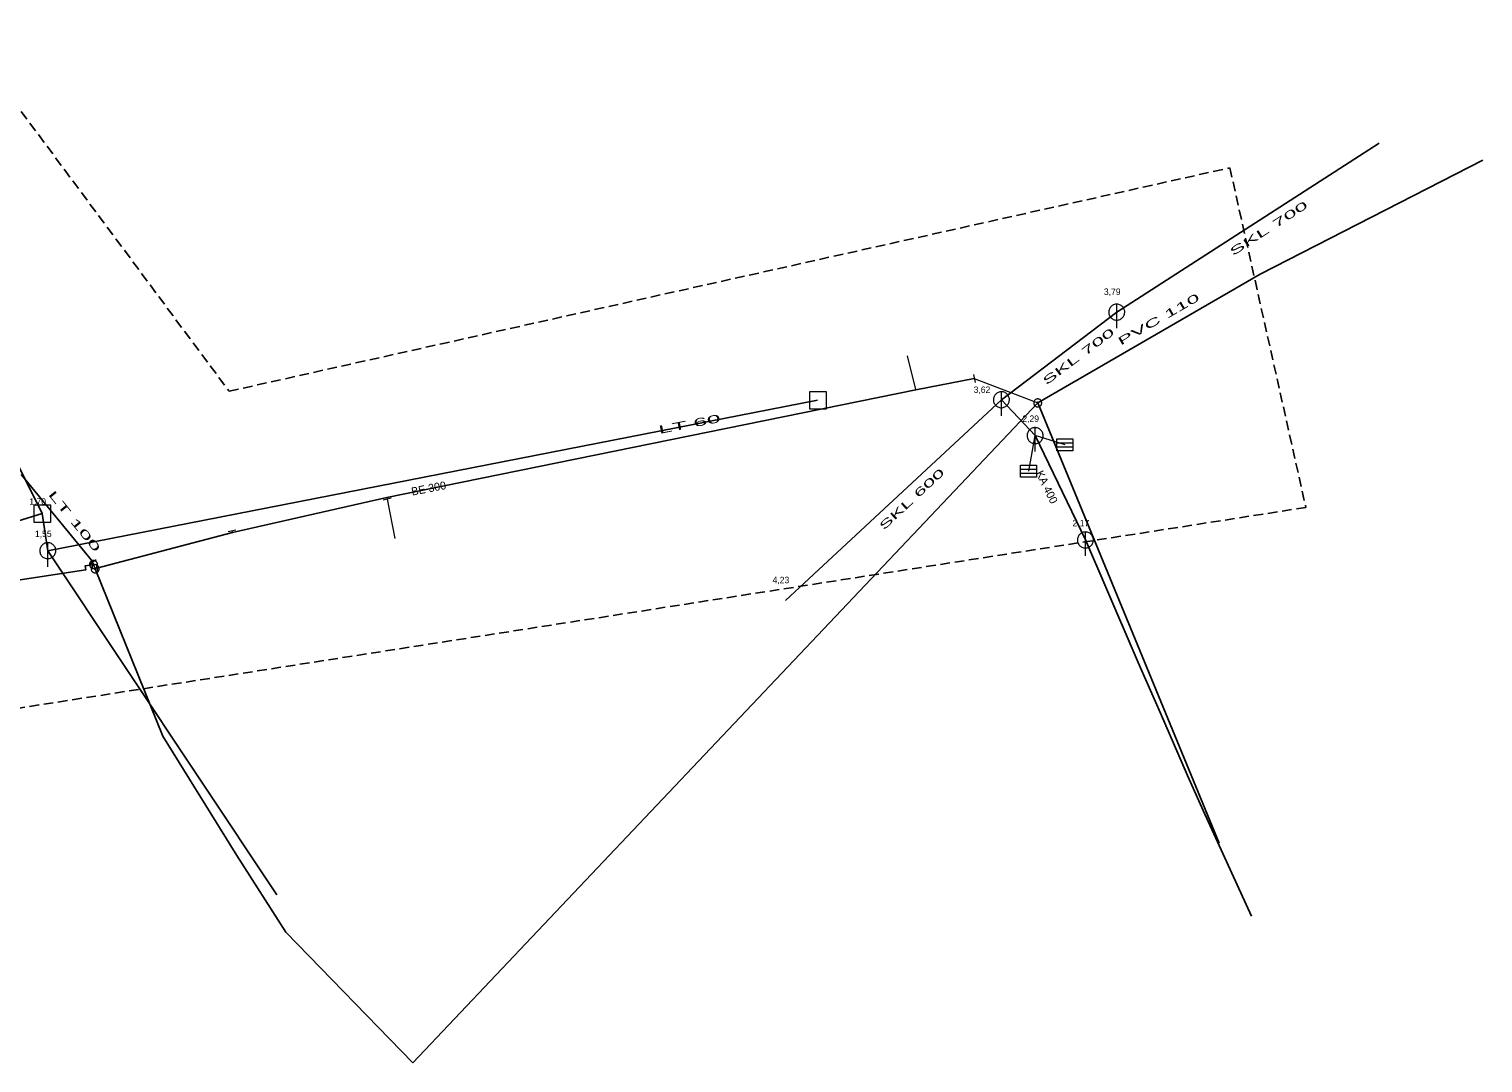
# Model space of a CAD drawing. Extents: x -689820 to -689363, y -975369 to -975062.
# Drawn here: x -689544.2 to -689362.6, y -975351.8 to -975222.7 of the extents above; entities that cross this region are included whole.
import ezdxf

# ---------------------------------------------------------------- set-up
doc = ezdxf.new("R2010")
doc.units = 0
doc.header["$LTSCALE"] = 0.4
doc.linetypes.add('MEDIUM_DASHED', pattern=[4.5, 3, -1.5])
doc.layers.add('1', color=7, linetype='Continuous')
for name, color, linetype, lineweight in [('11', 7, 'Continuous', 13), ('13', 7, 'Continuous', 13), ('14', 7, 'Continuous', 25), ('17', 7, 'Continuous', 25), ('22', 7, 'Continuous', 13), ('34', 7, 'Continuous', 13), ('47', 7, 'Continuous', 13), ('63', 7, 'MEDIUM_DASHED', 25)]:
    doc.layers.add(name, color=color, linetype=linetype, lineweight=lineweight)

msp = doc.modelspace()

# ---------------------------------------------------------------- linework, layer by layer
at = {"layer": '11'}
for p in [(-689419.3, -975277.91), (-689414.76, -975274.629)]:
    msp.add_line(p, (-689418.5, -975273.46), dxfattribs=at)
at = {"layer": '13'}
for p, q in [((-689433.4, -975267.707), (-689434.429, -975263.493)), ((-689499.459, -975281.399), (-689498.509, -975286.309))]:
    msp.add_line(p, q, dxfattribs=at)
at = {"layer": '14'}
for p, q in [((-689408.307, -975258.04), (-689375.534, -975236.952)), ((-689445.682, -975269.038), (-689541.87, -975287.838)), ((-689418.5, -975273.46), (-689422.719, -975268.98)), ((-689412.219, -975286.5), (-689418.5, -975273.46)), ((-689541.87, -975287.838), (-689542.572, -975283.204)), ((-689513.237, -975330.816), (-689541.87, -975287.838))]:
    msp.add_line(p, q, dxfattribs=at)
at = {"layer": '14', "lineweight": 13}
for p, q in [((-689426.099, -975266.339), (-689418.177, -975269.382)), ((-689433.388, -975267.761), (-689433.4, -975267.707)), ((-689499.505, -975281.209), (-689499.459, -975281.399)), ((-689518.795, -975285.558), (-689518.848, -975285.325)), ((-689536.162, -975289.569), (-689536.351, -975289.602)), ((-689536.162, -975289.569), (-689536.239, -975289.23)), ((-689535.949, -975290.109), (-689536.162, -975289.569)), ((-689535.721, -975290.003), (-689535.949, -975290.109))]:
    msp.add_line(p, q, dxfattribs=at)
at = {"layer": '14'}
for points in [[(-689449.708, -975294.055), (-689422.719, -975268.98), (-689408.307, -975258.04)], [(-689583.441, -975293.556), (-689564.324, -975289.938), (-689542.572, -975283.204), (-689553.342, -975261.657)], [(-689391.449, -975333.51), (-689397.489, -975320.28), (-689399.46, -975315.92), (-689402.838, -975308.133), (-689405.32, -975302.467), (-689405.75, -975301.5), (-689409.66, -975292.403), (-689412.219, -975286.5)]]:
    msp.add_lwpolyline(points, dxfattribs=at)
at = {"layer": '17'}
for p, q in [((-689418.177, -975269.382), (-689496.251, -975351.823)), ((-689395.493, -975324.391), (-689418.177, -975269.382)), ((-689536.239, -975289.23), (-689545.213, -975278.312))]:
    msp.add_line(p, q, dxfattribs=at)
for points in [[(-689362.55, -975239.05), (-689390.403, -975253.287), (-689418.177, -975269.382)], [(-689426.099, -975266.339), (-689433.388, -975267.761), (-689499.505, -975281.209), (-689518.795, -975285.558), (-689535.721, -975290.003)], [(-689536.351, -975289.602), (-689537.203, -975289.743), (-689537.12, -975290.232), (-689713.89, -975317.113)], [(-689496.251, -975351.823), (-689512.116, -975335.5), (-689518.26, -975325.93), (-689527.5, -975310.989), (-689535.949, -975290.109)]]:
    msp.add_lwpolyline(points, dxfattribs=at)
at = {"layer": '22'}
for p, q in [((-689408.307, -975260.04), (-689408.306, -975257.04)), ((-689422.719, -975270.98), (-689422.718, -975267.98)), ((-689418.5, -975275.46), (-689418.499, -975272.46)), ((-689415.771, -975274.372), (-689413.771, -975274.372)), ((-689415.771, -975274.872), (-689413.771, -975274.872)), ((-689420.311, -975277.653), (-689418.311, -975277.653)), ((-689420.311, -975278.153), (-689418.311, -975278.153)), ((-689541.87, -975289.838), (-689541.869, -975286.838)), ((-689412.219, -975288.5), (-689412.218, -975285.5))]:
    msp.add_line(p, q, dxfattribs=at)
for points in [[(-689407.307, -975258.04), (-689407.312, -975257.931), (-689407.33, -975257.823), (-689407.36, -975257.717), (-689407.4, -975257.616), (-689407.452, -975257.519), (-689407.514, -975257.429), (-689407.586, -975257.346), (-689407.666, -975257.272), (-689407.754, -975257.206), (-689407.848, -975257.151), (-689407.948, -975257.106), (-689408.053, -975257.073), (-689408.16, -975257.051), (-689408.269, -975257.041), (-689408.379, -975257.043), (-689408.487, -975257.057), (-689408.594, -975257.082), (-689408.697, -975257.119), (-689408.795, -975257.168), (-689408.887, -975257.226), (-689408.973, -975257.295), (-689409.05, -975257.372), (-689409.119, -975257.458), (-689409.178, -975257.55), (-689409.226, -975257.648), (-689409.263, -975257.751), (-689409.289, -975257.858), (-689409.303, -975257.966), (-689409.306, -975258.076), (-689409.296, -975258.185), (-689409.275, -975258.292), (-689409.241, -975258.396), (-689409.197, -975258.496), (-689409.142, -975258.591), (-689409.076, -975258.679), (-689409.002, -975258.759), (-689408.919, -975258.831), (-689408.829, -975258.893), (-689408.733, -975258.945), (-689408.631, -975258.986), (-689408.526, -975259.016), (-689408.418, -975259.034), (-689408.308, -975259.04), (-689408.199, -975259.034), (-689408.091, -975259.016), (-689407.986, -975258.987), (-689407.884, -975258.946), (-689407.787, -975258.894), (-689407.697, -975258.832), (-689407.614, -975258.761), (-689407.539, -975258.681), (-689407.474, -975258.593), (-689407.418, -975258.499), (-689407.374, -975258.399), (-689407.34, -975258.295), (-689407.318, -975258.187), (-689407.308, -975258.078)], [(-689446.662, -975267.948), (-689444.629, -975267.948), (-689444.629, -975270.141), (-689446.662, -975270.141)], [(-689421.719, -975268.98), (-689421.724, -975268.871), (-689421.742, -975268.763), (-689421.772, -975268.657), (-689421.812, -975268.556), (-689421.864, -975268.459), (-689421.926, -975268.369), (-689421.998, -975268.286), (-689422.078, -975268.212), (-689422.166, -975268.146), (-689422.26, -975268.091), (-689422.36, -975268.046), (-689422.465, -975268.013), (-689422.572, -975267.991), (-689422.681, -975267.981), (-689422.791, -975267.983), (-689422.899, -975267.997), (-689423.006, -975268.022), (-689423.109, -975268.059), (-689423.207, -975268.108), (-689423.299, -975268.166), (-689423.385, -975268.235), (-689423.462, -975268.312), (-689423.531, -975268.398), (-689423.59, -975268.49), (-689423.638, -975268.588), (-689423.675, -975268.691), (-689423.701, -975268.798), (-689423.715, -975268.906), (-689423.718, -975269.016), (-689423.708, -975269.125), (-689423.687, -975269.232), (-689423.653, -975269.336), (-689423.609, -975269.436), (-689423.554, -975269.531), (-689423.488, -975269.619), (-689423.414, -975269.699), (-689423.331, -975269.771), (-689423.241, -975269.833), (-689423.145, -975269.885), (-689423.043, -975269.926), (-689422.938, -975269.956), (-689422.83, -975269.974), (-689422.72, -975269.98), (-689422.611, -975269.974), (-689422.503, -975269.956), (-689422.398, -975269.927), (-689422.296, -975269.886), (-689422.199, -975269.834), (-689422.109, -975269.772), (-689422.026, -975269.701), (-689421.951, -975269.621), (-689421.886, -975269.533), (-689421.83, -975269.439), (-689421.786, -975269.339), (-689421.752, -975269.235), (-689421.73, -975269.127), (-689421.72, -975269.018)], [(-689417.5, -975273.46), (-689417.505, -975273.351), (-689417.523, -975273.243), (-689417.553, -975273.137), (-689417.593, -975273.036), (-689417.645, -975272.939), (-689417.707, -975272.849), (-689417.779, -975272.766), (-689417.859, -975272.692), (-689417.947, -975272.626), (-689418.041, -975272.571), (-689418.141, -975272.526), (-689418.246, -975272.493), (-689418.353, -975272.471), (-689418.462, -975272.461), (-689418.572, -975272.463), (-689418.68, -975272.477), (-689418.787, -975272.502), (-689418.89, -975272.539), (-689418.988, -975272.588), (-689419.08, -975272.646), (-689419.166, -975272.715), (-689419.243, -975272.792), (-689419.312, -975272.878), (-689419.371, -975272.97), (-689419.419, -975273.068), (-689419.456, -975273.171), (-689419.482, -975273.278), (-689419.496, -975273.386), (-689419.499, -975273.496), (-689419.489, -975273.605), (-689419.468, -975273.712), (-689419.434, -975273.816), (-689419.39, -975273.916), (-689419.335, -975274.011), (-689419.269, -975274.099), (-689419.195, -975274.179), (-689419.112, -975274.251), (-689419.022, -975274.313), (-689418.926, -975274.365), (-689418.824, -975274.406), (-689418.719, -975274.436), (-689418.611, -975274.454), (-689418.501, -975274.46), (-689418.392, -975274.454), (-689418.284, -975274.436), (-689418.179, -975274.407), (-689418.077, -975274.366), (-689417.98, -975274.314), (-689417.89, -975274.252), (-689417.807, -975274.181), (-689417.732, -975274.101), (-689417.667, -975274.013), (-689417.611, -975273.919), (-689417.567, -975273.819), (-689417.533, -975273.715), (-689417.511, -975273.607), (-689417.501, -975273.498)], [(-689415.771, -975273.872), (-689413.771, -975273.872), (-689413.771, -975275.372), (-689415.771, -975275.372)], [(-689420.311, -975277.153), (-689418.311, -975277.153), (-689418.311, -975278.653), (-689420.311, -975278.653)], [(-689543.552, -975282.114), (-689541.519, -975282.114), (-689541.519, -975284.307), (-689543.552, -975284.307)], [(-689540.87, -975287.838), (-689540.875, -975287.729), (-689540.893, -975287.621), (-689540.923, -975287.515), (-689540.963, -975287.414), (-689541.015, -975287.317), (-689541.077, -975287.227), (-689541.149, -975287.144), (-689541.229, -975287.07), (-689541.317, -975287.004), (-689541.411, -975286.949), (-689541.511, -975286.904), (-689541.616, -975286.871), (-689541.723, -975286.849), (-689541.832, -975286.839), (-689541.942, -975286.841), (-689542.05, -975286.855), (-689542.157, -975286.88), (-689542.26, -975286.917), (-689542.358, -975286.966), (-689542.45, -975287.024), (-689542.536, -975287.093), (-689542.613, -975287.17), (-689542.682, -975287.256), (-689542.741, -975287.348), (-689542.789, -975287.446), (-689542.826, -975287.549), (-689542.852, -975287.656), (-689542.866, -975287.764), (-689542.869, -975287.874), (-689542.859, -975287.983), (-689542.838, -975288.09), (-689542.804, -975288.194), (-689542.76, -975288.294), (-689542.705, -975288.389), (-689542.639, -975288.477), (-689542.565, -975288.557), (-689542.482, -975288.629), (-689542.392, -975288.691), (-689542.296, -975288.743), (-689542.194, -975288.784), (-689542.089, -975288.814), (-689541.981, -975288.832), (-689541.871, -975288.838), (-689541.762, -975288.832), (-689541.654, -975288.814), (-689541.549, -975288.785), (-689541.447, -975288.744), (-689541.35, -975288.692), (-689541.26, -975288.63), (-689541.177, -975288.559), (-689541.102, -975288.479), (-689541.037, -975288.391), (-689540.981, -975288.297), (-689540.937, -975288.197), (-689540.903, -975288.093), (-689540.881, -975287.985), (-689540.871, -975287.876)], [(-689411.219, -975286.5), (-689411.224, -975286.391), (-689411.242, -975286.283), (-689411.272, -975286.177), (-689411.312, -975286.076), (-689411.364, -975285.979), (-689411.426, -975285.889), (-689411.498, -975285.806), (-689411.578, -975285.732), (-689411.666, -975285.666), (-689411.76, -975285.611), (-689411.86, -975285.566), (-689411.965, -975285.533), (-689412.072, -975285.511), (-689412.181, -975285.501), (-689412.291, -975285.503), (-689412.399, -975285.517), (-689412.506, -975285.542), (-689412.609, -975285.579), (-689412.707, -975285.628), (-689412.799, -975285.686), (-689412.885, -975285.755), (-689412.962, -975285.832), (-689413.031, -975285.918), (-689413.09, -975286.01), (-689413.138, -975286.108), (-689413.175, -975286.211), (-689413.201, -975286.318), (-689413.215, -975286.426), (-689413.218, -975286.536), (-689413.208, -975286.645), (-689413.187, -975286.752), (-689413.153, -975286.856), (-689413.109, -975286.956), (-689413.054, -975287.051), (-689412.988, -975287.139), (-689412.914, -975287.219), (-689412.831, -975287.291), (-689412.741, -975287.353), (-689412.645, -975287.405), (-689412.543, -975287.446), (-689412.438, -975287.476), (-689412.33, -975287.494), (-689412.22, -975287.5), (-689412.111, -975287.494), (-689412.003, -975287.476), (-689411.898, -975287.447), (-689411.796, -975287.406), (-689411.699, -975287.354), (-689411.609, -975287.292), (-689411.526, -975287.221), (-689411.451, -975287.141), (-689411.386, -975287.053), (-689411.33, -975286.959), (-689411.286, -975286.859), (-689411.252, -975286.755), (-689411.23, -975286.647), (-689411.22, -975286.538)]]:
    msp.add_lwpolyline(points, close=True, dxfattribs=at)
at = {"layer": '34'}
for p, q in [((-689426.187, -975265.846), (-689426.011, -975266.831)), ((-689433.889, -975267.809), (-689432.91, -975267.605)), ((-689498.972, -975281.282), (-689499.945, -975281.514)), ((-689519.335, -975285.435), (-689518.36, -975285.215)), ((-689536.653, -975289.509), (-689535.824, -975288.951)), ((-689536.439, -975289.109), (-689536.263, -975290.094)), ((-689535.809, -975289.51), (-689535.633, -975290.495))]:
    msp.add_line(p, q, dxfattribs=at)
at = {"layer": '47'}
for points in [[(-689417.919, -975269.81), (-689417.876, -975269.781), (-689417.835, -975269.747), (-689417.8, -975269.709), (-689417.767, -975269.668), (-689417.739, -975269.624), (-689417.716, -975269.576), (-689417.699, -975269.527), (-689417.686, -975269.476), (-689417.679, -975269.425), (-689417.677, -975269.372), (-689417.68, -975269.32), (-689417.69, -975269.269), (-689417.704, -975269.218), (-689417.724, -975269.17), (-689417.748, -975269.124), (-689417.777, -975269.081), (-689417.811, -975269.04), (-689417.849, -975269.004), (-689417.89, -975268.972), (-689417.934, -975268.944), (-689417.982, -975268.921), (-689418.031, -975268.903), (-689418.082, -975268.891), (-689418.133, -975268.883), (-689418.186, -975268.882), (-689418.238, -975268.885), (-689418.29, -975268.894), (-689418.34, -975268.909), (-689418.388, -975268.929), (-689418.434, -975268.953), (-689418.477, -975268.982), (-689418.518, -975269.016), (-689418.555, -975269.054), (-689418.586, -975269.095), (-689418.614, -975269.139), (-689418.637, -975269.186), (-689418.655, -975269.236), (-689418.668, -975269.286), (-689418.675, -975269.338), (-689418.676, -975269.391), (-689418.673, -975269.443), (-689418.664, -975269.494), (-689418.649, -975269.545), (-689418.629, -975269.593), (-689418.605, -975269.639), (-689418.576, -975269.682), (-689418.542, -975269.723), (-689418.505, -975269.759), (-689418.463, -975269.791), (-689418.419, -975269.819), (-689418.372, -975269.842), (-689418.323, -975269.859), (-689418.272, -975269.872), (-689418.22, -975269.879), (-689418.167, -975269.881), (-689418.115, -975269.878), (-689418.064, -975269.868), (-689418.013, -975269.854), (-689417.965, -975269.834)], [(-689418.134, -975269.452), (-689418.127, -975269.447), (-689418.121, -975269.441), (-689418.115, -975269.435), (-689418.11, -975269.429), (-689418.105, -975269.421), (-689418.101, -975269.413), (-689418.098, -975269.405), (-689418.096, -975269.397), (-689418.095, -975269.389), (-689418.095, -975269.38), (-689418.095, -975269.371), (-689418.097, -975269.363), (-689418.099, -975269.355), (-689418.102, -975269.347), (-689418.106, -975269.339), (-689418.111, -975269.332), (-689418.117, -975269.326), (-689418.123, -975269.32), (-689418.129, -975269.315), (-689418.137, -975269.31), (-689418.145, -975269.306), (-689418.153, -975269.303), (-689418.161, -975269.301), (-689418.17, -975269.299), (-689418.178, -975269.3), (-689418.187, -975269.3), (-689418.195, -975269.302), (-689418.203, -975269.304), (-689418.211, -975269.307), (-689418.219, -975269.311), (-689418.226, -975269.316), (-689418.232, -975269.322), (-689418.238, -975269.328), (-689418.243, -975269.334), (-689418.248, -975269.342), (-689418.252, -975269.349), (-689418.255, -975269.358), (-689418.257, -975269.366), (-689418.259, -975269.375), (-689418.258, -975269.383), (-689418.258, -975269.392), (-689418.256, -975269.4), (-689418.254, -975269.408), (-689418.251, -975269.416), (-689418.247, -975269.424), (-689418.242, -975269.431), (-689418.236, -975269.437), (-689418.23, -975269.443), (-689418.224, -975269.448), (-689418.216, -975269.453), (-689418.209, -975269.457), (-689418.2, -975269.46), (-689418.192, -975269.462), (-689418.184, -975269.463), (-689418.175, -975269.463), (-689418.166, -975269.463), (-689418.158, -975269.461), (-689418.15, -975269.459), (-689418.142, -975269.456)], [(-689535.904, -975289.997), (-689535.861, -975289.968), (-689535.82, -975289.934), (-689535.785, -975289.896), (-689535.752, -975289.855), (-689535.724, -975289.811), (-689535.701, -975289.763), (-689535.684, -975289.714), (-689535.671, -975289.663), (-689535.664, -975289.612), (-689535.662, -975289.559), (-689535.665, -975289.507), (-689535.675, -975289.456), (-689535.689, -975289.405), (-689535.709, -975289.357), (-689535.733, -975289.311), (-689535.762, -975289.268), (-689535.796, -975289.227), (-689535.834, -975289.191), (-689535.875, -975289.159), (-689535.919, -975289.131), (-689535.967, -975289.108), (-689536.016, -975289.09), (-689536.067, -975289.078), (-689536.118, -975289.07), (-689536.171, -975289.069), (-689536.223, -975289.072), (-689536.275, -975289.081), (-689536.325, -975289.096), (-689536.373, -975289.116), (-689536.419, -975289.14), (-689536.462, -975289.169), (-689536.503, -975289.203), (-689536.54, -975289.241), (-689536.571, -975289.282), (-689536.599, -975289.326), (-689536.622, -975289.373), (-689536.64, -975289.423), (-689536.653, -975289.473), (-689536.66, -975289.525), (-689536.661, -975289.578), (-689536.658, -975289.63), (-689536.649, -975289.681), (-689536.634, -975289.732), (-689536.614, -975289.78), (-689536.59, -975289.826), (-689536.561, -975289.869), (-689536.527, -975289.91), (-689536.49, -975289.946), (-689536.448, -975289.978), (-689536.404, -975290.006), (-689536.357, -975290.029), (-689536.308, -975290.046), (-689536.257, -975290.059), (-689536.205, -975290.066), (-689536.152, -975290.068), (-689536.1, -975290.065), (-689536.049, -975290.055), (-689535.998, -975290.041), (-689535.95, -975290.021)], [(-689536.132, -975289.643), (-689536.179, -975289.665), (-689536.224, -975289.692), (-689536.266, -975289.723), (-689536.305, -975289.758), (-689536.34, -975289.797), (-689536.37, -975289.84), (-689536.395, -975289.886), (-689536.416, -975289.934), (-689536.432, -975289.983), (-689536.443, -975290.035), (-689536.448, -975290.087), (-689536.447, -975290.139), (-689536.442, -975290.191), (-689536.43, -975290.242), (-689536.414, -975290.292), (-689536.392, -975290.339), (-689536.365, -975290.384), (-689536.334, -975290.427), (-689536.299, -975290.465), (-689536.26, -975290.5), (-689536.217, -975290.53), (-689536.171, -975290.556), (-689536.123, -975290.577), (-689536.074, -975290.593), (-689536.022, -975290.603), (-689535.97, -975290.608), (-689535.917, -975290.608), (-689535.866, -975290.602), (-689535.815, -975290.59), (-689535.765, -975290.574), (-689535.718, -975290.552), (-689535.673, -975290.525), (-689535.63, -975290.495), (-689535.592, -975290.459), (-689535.557, -975290.42), (-689535.527, -975290.378), (-689535.5, -975290.332), (-689535.48, -975290.284), (-689535.464, -975290.234), (-689535.454, -975290.182), (-689535.449, -975290.13), (-689535.449, -975290.078), (-689535.455, -975290.026), (-689535.467, -975289.975), (-689535.483, -975289.925), (-689535.505, -975289.878), (-689535.532, -975289.833), (-689535.562, -975289.791), (-689535.598, -975289.752), (-689535.637, -975289.717), (-689535.679, -975289.687), (-689535.725, -975289.661), (-689535.773, -975289.641), (-689535.823, -975289.625), (-689535.875, -975289.614), (-689535.927, -975289.609), (-689535.978, -975289.61), (-689536.031, -975289.615), (-689536.082, -975289.627)], [(-689536.119, -975289.639), (-689536.112, -975289.634), (-689536.106, -975289.628), (-689536.1, -975289.622), (-689536.095, -975289.616), (-689536.09, -975289.608), (-689536.086, -975289.6), (-689536.083, -975289.592), (-689536.081, -975289.584), (-689536.08, -975289.576), (-689536.08, -975289.567), (-689536.08, -975289.558), (-689536.082, -975289.55), (-689536.084, -975289.542), (-689536.087, -975289.534), (-689536.091, -975289.526), (-689536.096, -975289.519), (-689536.102, -975289.513), (-689536.108, -975289.507), (-689536.114, -975289.502), (-689536.122, -975289.497), (-689536.13, -975289.493), (-689536.138, -975289.49), (-689536.146, -975289.488), (-689536.155, -975289.486), (-689536.163, -975289.487), (-689536.172, -975289.487), (-689536.18, -975289.489), (-689536.188, -975289.491), (-689536.196, -975289.494), (-689536.204, -975289.498), (-689536.211, -975289.503), (-689536.217, -975289.509), (-689536.223, -975289.515), (-689536.228, -975289.521), (-689536.233, -975289.529), (-689536.237, -975289.536), (-689536.24, -975289.545), (-689536.242, -975289.553), (-689536.244, -975289.562), (-689536.243, -975289.57), (-689536.243, -975289.579), (-689536.241, -975289.587), (-689536.239, -975289.595), (-689536.236, -975289.603), (-689536.232, -975289.611), (-689536.227, -975289.618), (-689536.221, -975289.624), (-689536.215, -975289.63), (-689536.209, -975289.635), (-689536.201, -975289.64), (-689536.194, -975289.644), (-689536.185, -975289.647), (-689536.177, -975289.649), (-689536.169, -975289.65), (-689536.16, -975289.65), (-689536.151, -975289.65), (-689536.143, -975289.648), (-689536.135, -975289.646), (-689536.127, -975289.643)], [(-689535.979, -975290.032), (-689535.987, -975290.036), (-689535.994, -975290.04), (-689536, -975290.045), (-689536.007, -975290.051), (-689536.013, -975290.057), (-689536.017, -975290.065), (-689536.022, -975290.072), (-689536.025, -975290.08), (-689536.027, -975290.088), (-689536.03, -975290.096), (-689536.03, -975290.105), (-689536.03, -975290.114), (-689536.029, -975290.122), (-689536.028, -975290.13), (-689536.025, -975290.139), (-689536.021, -975290.147), (-689536.017, -975290.154), (-689536.012, -975290.16), (-689536.006, -975290.167), (-689536, -975290.173), (-689535.992, -975290.177), (-689535.985, -975290.182), (-689535.977, -975290.185), (-689535.969, -975290.188), (-689535.961, -975290.19), (-689535.952, -975290.19), (-689535.943, -975290.19), (-689535.935, -975290.189), (-689535.927, -975290.188), (-689535.918, -975290.185), (-689535.91, -975290.181), (-689535.903, -975290.177), (-689535.897, -975290.172), (-689535.89, -975290.166), (-689535.884, -975290.16), (-689535.879, -975290.153), (-689535.875, -975290.145), (-689535.872, -975290.137), (-689535.869, -975290.129), (-689535.867, -975290.121), (-689535.867, -975290.112), (-689535.867, -975290.103), (-689535.868, -975290.095), (-689535.869, -975290.087), (-689535.872, -975290.078), (-689535.876, -975290.07), (-689535.88, -975290.063), (-689535.885, -975290.057), (-689535.891, -975290.05), (-689535.897, -975290.044), (-689535.904, -975290.039), (-689535.912, -975290.035), (-689535.92, -975290.032), (-689535.928, -975290.03), (-689535.936, -975290.027), (-689535.945, -975290.027), (-689535.954, -975290.027), (-689535.962, -975290.028), (-689535.97, -975290.029)]]:
    msp.add_lwpolyline(points, close=True, dxfattribs=at)
at = {"layer": '63'}
msp.add_lwpolyline([(-689662.123, -975114.404), (-689588.993, -975102.123), (-689588.993, -975102.123), (-689580.62, -975185.301), (-689580.62, -975185.301), (-689519.213, -975267.921), (-689519.213, -975267.921), (-689394.167, -975240.009), (-689394.167, -975240.009), (-689384.677, -975282.435), (-689384.677, -975282.435), (-689764.282, -975341.609), (-689764.282, -975341.609), (-689752.559, -975296.95), (-689752.559, -975296.95), (-689602.391, -975253.965), (-689627.512, -975210.422), (-689603.508, -975253.965), (-689648.167, -975167.437), (-689648.167, -975167.437)], close=True, dxfattribs=at)

# ---------------------------------------------------------------- texts
at = {"layer": '1'}
for s, rotation, width, p in [('SKL 700 ', 33, 2.2, (-689393.789, -975251.059)), ('PVC 110 ', 30, 2.15, (-689407.812, -975262.236)), ('SKL 700 ', 37, 2.1, (-689417.1, -975267.207)), ('LT 60 ', 11, 2.3, (-689465.457, -975273.252)), ('SKL 600 ', 43, 2.05, (-689437.426, -975285.353)), ('LT 100', 309, 2.25, (-689541.87, -975280.827))]:
    msp.add_text(s, height=1, rotation=rotation, dxfattribs=dict(at, width=width)).set_placement(p)
for s, p in [('3,79', (-689409.907, -975255.887)), ('3,62', (-689426.183, -975268.132)), ('2,29', (-689420.1, -975271.748)), ('1,70', (-689544.172, -975282.089)), ('2,17', (-689413.819, -975284.788)), ('1,55', (-689543.47, -975286.126)), ('4,23', (-689451.308, -975291.903))]:
    msp.add_text(s, height=0.8, dxfattribs=at).set_placement(p)
for s, rotation, p in [('KA 400', 296, (-689418.45, -975278.138)), ('BE 300', 11, (-689496.339, -975280.962))]:
    msp.add_text(s, height=1, rotation=rotation, dxfattribs=at).set_placement(p)

doc.saveas('drawing.dxf')
